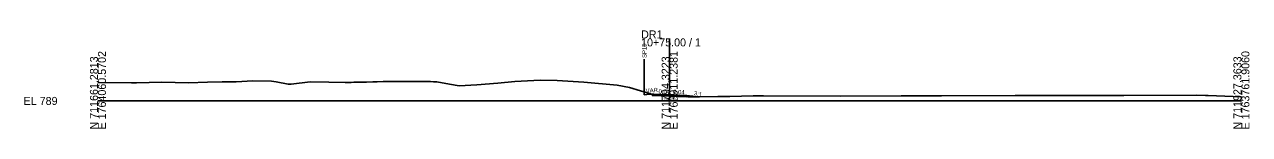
# Model space of a CAD drawing. Extents: x -26 to 403, y -10 to 2023.
# Drawn here: x -25.7 to 402.8, y 1490.3 to 1524.7 of the extents above; entities that cross this region are included whole.
import ezdxf

# ---------------------------------------------------------------- set-up
doc = ezdxf.new("R2010")
doc.units = 0
for name, color, linetype in [('Exist Cross Section Cell', 7, 'Continuous'), ('Exist XS Center Line Elevation Label', 7, 'Continuous'), ('Exist XS Ground Line', 7, 'Continuous'), ('Prop CMT Pvmt Surface', 7, 'Continuous'), ('Prop CMT Slope Grass', 7, 'Continuous'), ('Prop CMT Subgrade Earthwork', 7, 'Continuous'), ('Prop XS Earthwork Shape', 7, 'Continuous'), ('Prop XS Shear Point Element', 7, 'Continuous'), ('Prop XS Side Slope Text', 7, 'Continuous')]:
    doc.layers.add(name, color=color, linetype=linetype)

msp = doc.modelspace()

# ---------------------------------------------------------------- linework, layer by layer
at = {"layer": 'Exist Cross Section Cell'}
for p, q in [((200, 1500), (200, 1521.91)), ((0, 1500), (200, 1500)), ((200, 1500), (400, 1500))]:
    msp.add_line(p, q, dxfattribs=at)
at = {"layer": 'Exist XS Ground Line'}
msp.add_lwpolyline([(0, 1506.49), (11.79, 1506.36), (13.52, 1506.34), (22.31, 1506.57), (31.66, 1506.34), (38.34, 1506.53), (43.48, 1506.65), (45.07, 1506.69), (48.32, 1506.72), (54.13, 1507.05), (60.66, 1506.95), (62.34, 1506.66), (66.54, 1505.9), (67.56, 1505.9), (74.22, 1506.74), (80.81, 1506.6), (86.53, 1506.42), (86.93, 1506.42), (88.59, 1506.49), (89.49, 1506.52), (90.15, 1506.54), (92.84, 1506.61), (93.91, 1506.63), (96.19, 1506.69), (97.67, 1506.72), (99.79, 1506.76), (101.65, 1506.81), (102.36, 1506.82), (103.35, 1506.82), (104.38, 1506.82), (105.09, 1506.81), (106.23, 1506.8), (108.94, 1506.79), (109.58, 1506.79), (112.93, 1506.77), (114.8, 1506.76), (116.28, 1506.76), (117.39, 1506.74), (118.01, 1506.72), (118.5, 1506.69), (122.95, 1505.91), (126.42, 1505.26), (132.5, 1505.69), (139.85, 1506.23), (145.83, 1506.8), (154.65, 1507.3), (160.64, 1507.18), (170.03, 1506.52), (181.6, 1505.53), (185.9, 1504.7), (193.65, 1502.42), (196.14, 1502.17), (200, 1501.93), (203.78, 1501.7), (206.25, 1501.52), (206.6, 1501.44), (210.49, 1501.4), (216.88, 1501.58), (219.42, 1501.59), (221, 1501.59), (229.24, 1501.76), (231.24, 1501.79), (232.79, 1501.79), (259.76, 1501.68), (280.96, 1501.82), (288.33, 1501.83), (295.05, 1501.84), (320.81, 1501.87), (324.38, 1501.88), (329.02, 1501.88), (358.9, 1501.89), (384.15, 1501.99), (387.42, 1501.92), (387.75, 1501.89), (388.4, 1501.85), (400, 1501.45)], dxfattribs=at)
at = {"layer": 'Prop CMT Pvmt Surface'}
for q in [(194, 1502.36), (206, 1501.88)]:
    msp.add_line((200, 1502.12), q, dxfattribs=at)
at = {"layer": 'Prop CMT Slope Grass'}
for p, q in [((191.12, 1502.17), (191.12, 1503.17)), ((192, 1502.2), (191.12, 1502.17)), ((208, 1501.72), (208.9, 1501.42))]:
    msp.add_line(p, q, dxfattribs=at)
for points in [[(194, 1502.36), (192, 1502.2)], [(206, 1501.88), (208, 1501.72)]]:
    msp.add_lwpolyline(points, dxfattribs=at)
at = {"layer": 'Prop CMT Subgrade Earthwork'}
for p, q in [((193.98, 1501.86), (193.52, 1502.32)), ((199.98, 1501.62), (193.98, 1501.86)), ((199.98, 1501.62), (205.98, 1501.38)), ((205.98, 1501.38), (206.44, 1501.84))]:
    msp.add_line(p, q, dxfattribs=at)
at = {"layer": 'Prop XS Earthwork Shape'}
for points in [[(191.12, 1503.17), (193.65, 1502.42), (194.5, 1502.34), (194, 1502.36), (193.52, 1502.32), (192, 1502.2), (191.12, 1502.17)], [(205.98, 1501.38), (206.13, 1501.53), (203.78, 1501.7), (200, 1501.93), (196.14, 1502.17), (194.5, 1502.34), (194, 1502.36), (193.52, 1502.32), (193.98, 1501.86), (199.98, 1501.62)], [(206.13, 1501.53), (206.25, 1501.52), (206.6, 1501.44), (208.9, 1501.42), (208, 1501.72), (206.44, 1501.84)]]:
    msp.add_lwpolyline(points, close=True, dxfattribs=at)
at = {"layer": 'Prop XS Shear Point Element'}
msp.add_line((191.12, 1502.17), (191.12, 1514.64), dxfattribs=at)

# ---------------------------------------------------------------- texts
at = {"layer": 'Exist Cross Section Cell'}
for s, p in [('10+75.00 / 1', (190, 1519.11)), ('DR1', (190, 1521.91)), ('EL 789', (-26, 1498.6))]:
    msp.add_text(s, height=2.8, dxfattribs=at).set_placement(p)
for s, p in [('E 1764060.5702', (2.8, 1490)), ('E 1763911.2381', (202.8, 1490)), ('E 1763761.9060', (402.8, 1490)), ('N 711661.2813', (0, 1490)), ('N 711794.3223', (200, 1490)), ('N 711927.3633', (400, 1490))]:
    msp.add_text(s, height=2.8, rotation=90, dxfattribs=at).set_placement(p)
at = {"layer": 'Exist XS Center Line Elevation Label'}
msp.add_text('790.93', height=1, dxfattribs=at).set_placement((197.88, 1499.93))
at = {"layer": 'Prop XS Shear Point Element'}
msp.add_text('SP10', height=1.5, rotation=90, dxfattribs=at).set_placement((191.9, 1515.06))
at = {"layer": 'Prop XS Side Slope Text'}
for s, rotation, p in [('VAR.', 5.2786, (191.69, 1502.77)), ('0.04', 357.7094, (196.08, 1502.63)), ('0.04', 357.7094, (201.19, 1502.45)), ('3:1', 345.9638, (208.32, 1502.09))]:
    msp.add_text(s, height=1.5, rotation=rotation, dxfattribs=at).set_placement(p)

doc.saveas('drawing.dxf')
